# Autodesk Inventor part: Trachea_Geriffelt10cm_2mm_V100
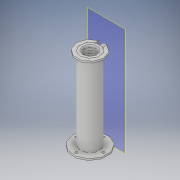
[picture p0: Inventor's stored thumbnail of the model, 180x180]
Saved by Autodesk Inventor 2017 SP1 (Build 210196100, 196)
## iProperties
Part Number: Trachea_Geriffelt10cm_2mm_V100
Material: Generisch
Document SubType Name: Modeling
Designer: haesner
Density: 1 g/cm^3
Appearance: Vorgabe
Part Number: Trachea_Geriffelt9cm_V100_3D-Druck
Author: haesner
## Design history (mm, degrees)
sketch "Skizze1"
  geometry: L1 (-14.4, 0)-(2.4, 0) reference; L2 (-9, 0)-(-12, 0); L3 (-12, 102)-(-12, 0); L4 (0, -20.4)-(0, 122.4) reference; L5 (-8, 0)-(-8, 102); L6 (-10, 102)-(-10, 0); L7 (-9, 102)-(-12, 102); A1 r 1.625 centre (-9.625, 4.5) between (-9, 3) and (-9, 6); A2 r 1.625 centre (-8.375, 1.5) between (-9, 3) and (-9, 0); A3 r 1.625 centre (-9.625, 10.5) between (-9, 9) and (-9, 12); A4 r 1.625 centre (-8.375, 7.5) between (-9, 9) and (-9, 6); A5 r 1.625 centre (-9.625, 16.5) between (-9, 15) and (-9, 18); A6 r 1.625 centre (-8.375, 13.5) between (-9, 15) and (-9, 12); A7 r 1.625 centre (-8.375, 19.5) between (-9, 21) and (-9, 18); A8 r 1.625 centre (-9.625, 22.5) between (-9, 21) and (-9, 24); A9 r 1.625 centre (-8.375, 25.5) between (-9, 27) and (-9, 24); A10 r 1.625 centre (-9.625, 28.5) between (-9, 27) and (-9, 30); A11 r 1.625 centre (-9.625, 46.5) between (-9, 45) and (-9, 48); A12 r 1.625 centre (-8.375, 43.5) between (-9, 45) and (-9, 42); A13 r 1.625 centre (-9.625, 40.5) between (-9, 39) and (-9, 42); A14 r 1.625 centre (-8.375, 37.5) between (-9, 39) and (-9, 36); A15 r 1.625 centre (-9.625, 34.5) between (-9, 33) and (-9, 36); A16 r 1.625 centre (-8.375, 31.5) between (-9, 33) and (-9, 30); A17 r 1.625 centre (-8.375, 49.5) between (-9, 51) and (-9, 48); A18 r 1.625 centre (-9.625, 52.5) between (-9, 51) and (-9, 54); A19 r 1.625 centre (-8.375, 55.5) between (-9, 57) and (-9, 54); A20 r 1.625 centre (-9.625, 58.5) between (-9, 57) and (-9, 60); A21 r 1.625 centre (-9.625, 70.5) between (-9, 69) and (-9, 72); A22 r 1.625 centre (-8.375, 67.5) between (-9, 69) and (-9, 66); A23 r 1.625 centre (-9.625, 64.5) between (-9, 63) and (-9, 66); A24 r 1.625 centre (-8.375, 61.5) between (-9, 63) and (-9, 60); A25 r 1.625 centre (-8.375, 85.5) between (-9, 87) and (-9, 84); A26 r 1.625 centre (-9.625, 76.5) between (-9, 75) and (-9, 78); A27 r 1.625 centre (-8.375, 73.5) between (-9, 75) and (-9, 72); A28 r 1.625 centre (-9.625, 82.5) between (-9, 81) and (-9, 84); A29 r 1.625 centre (-8.375, 79.5) between (-9, 81) and (-9, 78); A30 r 1.625 centre (-9.625, 88.5) between (-9, 87) and (-9, 90); A31 r 1.625 centre (-8.375, 91.5) between (-8.89, 93.041) and (-9, 90); A32 r 1.625 centre (-9.625, 94.5) between (-9, 93) and (-9, 96); A33 r 1.625 centre (-8.375, 97.5) between (-9, 99) and (-9, 96); A34 r 1.625 centre (-9.625, 100.5) between (-9, 99) and (-9, 102); 2 further points
  constraints: 69 point on circle, 34 centre point, 33 tangent, 19 equal radius, 10 end point, 5 point on line, 2 vertical, 1 horizontal, 1 horizontal alignment, 1 perpendicular, 37 other
  dimensions: "d4" = 3 distance of A1.start L2.start; "d5" = 3 distance of A1.end A3.start; "d6" = 3 distance of A3.end A5.start; "d11" = 3 distance of A5.end A7.start; "d12" = 3 distance of A8.end A9.start; "d20" = 3 distance of A10.end A15.start; "d21" = 3 distance of A14.end A13.start; "d22" = 3 distance of A12.end A11.start; "d27" = 3 distance of A11.end A17.start; "d28" = 3 distance of A18.end A19.start; "d31" = 3 distance of A20.end A23.start; "d32" = 3 distance of A22.end A21.start; "d33" = 3 distance of A21.end A26.start; "d34" = 3 distance of A26.end A28.start; "d35" = 3 distance of A25.end A25.start; "d89" = 12 distance from line of point (0, 0) L3; "d96" = 9 dimension on L4; "d97" = 102 distance of L3.start L2.end; "d119" = 8 distance between parallel lines of L4 L5; "d120" = 10 distance between parallel lines of L4 L6
revolve "Umdrehung2" sketch "Skizze1" stored, may be unused: angle "d121" = 90 deg
sketch "Skizze2"
  geometry: C1 r 21 at (0, 0); C2 r 12 at (0, 0); 1 further point
  constraints: 2 centre point, 1 coincident
  dimensions: "d44" = 42 diameter of C1
extrude "Extrusion1" join sketch "Skizze2" distance "d45" = 2; taper "d46" = 0 deg
workplane "Arbeitsebene2"
sketch "Skizze9"
  geometry: L1 (5, 10.909)-(5, 15.724); L2 (-5, 15.724)-(-5, 10.909); L3 (-23.1, 0)-(23.1, 0); L4 (0, -22.945)-(0, 22.169); A1 r 16.5 centre (0, 0) between (-5, 15.724) and (5, 15.724); A2 r 12 centre (0, 0) between (-5, 10.909) and (5, 10.909); 1 further point
  constraints: 8 end point, 4 point on circle, 2 centre point, 1 coincident, 1 parallel, 1 other
  dimensions: "d90" = 33 diameter of A1; "d108" = 10 distance between parallel lines of L1 L2; "d109" = 12 radius of A2; "d110" = 16.5 radius of A1 (derived)
extrude "Extrusion6" join sketch "Skizze9" distance "d91" = 2; taper "d92" = 0 deg
sketch "Skizze10"
  geometry: L1 (0, -20.4)-(0, 122.4) reference; L2 (16.8, 0)-(-16.8, 0) reference; C1 r 3 at (0, 97); 1 further point
  constraints: 1 centre point, 1 point on line
  dimensions: "d98" = 6 diameter of C1; "d99" = 97 distance from line of L2 C1.centre
extrude "Extrusion10" cut sketch "Skizze10" distance "d122" = 9; taper "d123" = 0 deg
sketch "Skizze11"
  geometry: 2 further points
  constraints: 1 other
extrude "Extrusion8" join sketch "Skizze11" distance "d102" = 8; taper "d103" = 0 deg
sketch "Skizze12"
  geometry: L1 (3, 0)-(-3, 0); L2 (-2.236, -2)-(2.236, -2); C1 r 0.75 at (0, 0); A1 r 3 centre (0, 0) between (-2.236, -2) and (2.236, -2); A2 r 3 centre (0, 0) between (3, 0) and (-3, 0); 1 further point
  constraints: 4 end point, 4 point on circle, 3 centre point, 1 coincident
  dimensions: "d104" = 1.5 diameter of C1
extrude "Extrusion9" cut sketch "Skizze12" distance "d105" = 18; taper "d106" = 0 deg
sketch "Skizze13"
  geometry: L1 (0, 16.5)-(-16.5, 0); L2 (-16.5, 0)-(0, -16.5); L3 (0, -16.5)-(16.5, 0); L4 (16.5, 0)-(0, 16.5); L5 (37.479, 0)-(-30.746, 0); L6 (0, -39.011)-(0, 31.002); 1 further point
  constraints: 12 end point, 3 point on line, 2 parallel, 2 perpendicular
  dimensions: "d111" = 16.5 distance from line of L5 L1.start
hole "Bohrung3" sketch "Skizze13" diameter "d112" = 3; stored, may be unused: countersink angle "d116" = 90 deg, drill point angle "d118" = 118 deg; dims "d113" = 6, "d114" = 4, "d115" = 2, "d117" = 8
fillet "Rundung2" dims "d124" = 0.5
node "Volumenkörper1"
node "Volumenkörper2"
